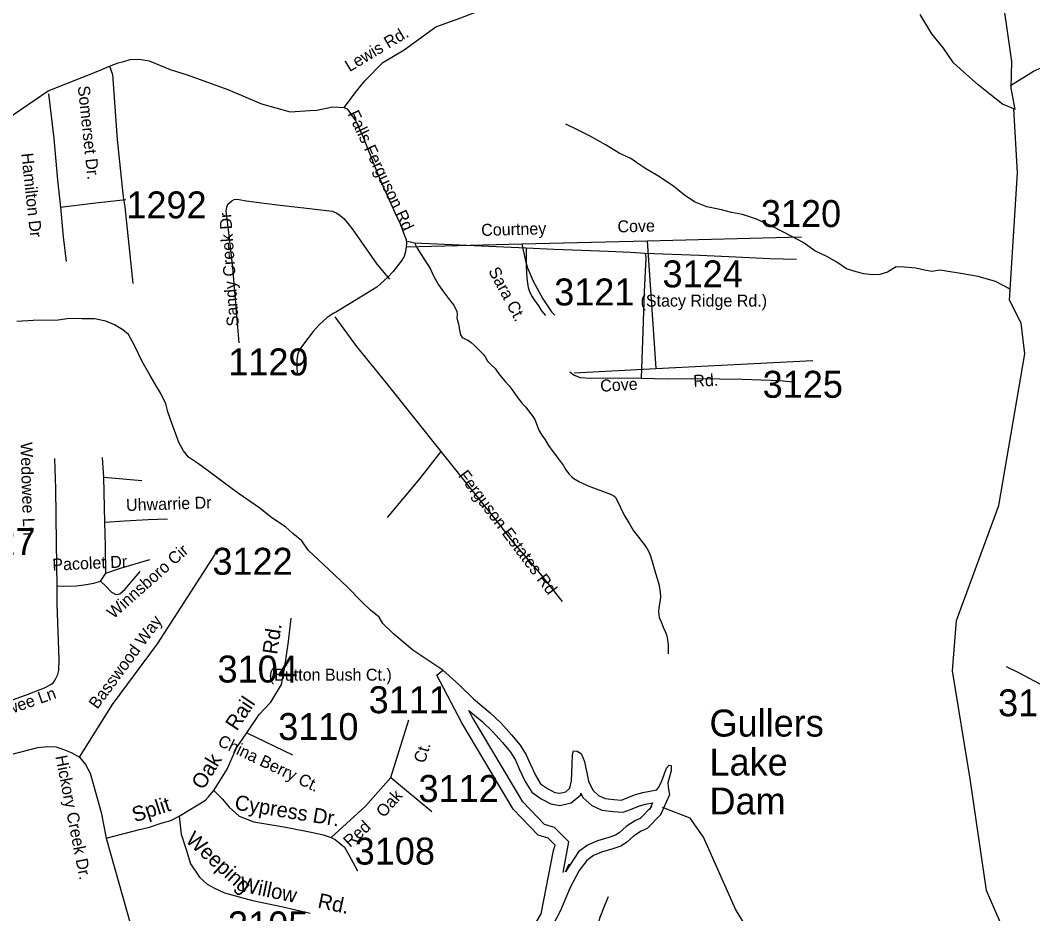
# Model space of a CAD drawing. Extents: x 1268485 to 1426702, y 514839 to 616766.
# Drawn here: x 1330300 to 1335842, y 535398 to 540290 of the extents above; entities that cross this region are included whole.
import ezdxf

# ---------------------------------------------------------------- set-up
doc = ezdxf.new("R2010")
doc.units = 0
for name, color, linetype in [('Old_Level_10', 7, 'Continuous'), ('Old_Level_11', 7, 'Continuous'), ('Old_Level_21', 7, 'Continuous'), ('Old_Level_32', 7, 'Continuous'), ('Old_Level_35', 7, 'Continuous'), ('Old_Level_58', 7, 'Continuous'), ('Old_Level_59', 7, 'Continuous'), ('Old_Level_60', 7, 'Continuous'), ('Old_Level_61', 7, 'Continuous'), ('Old_Level_62', 7, 'Continuous'), ('Old_Level_8', 7, 'Continuous')]:
    doc.layers.add(name, color=color, linetype=linetype)

msp = doc.modelspace()

# ---------------------------------------------------------------- linework, layer by layer
at = {"layer": 'Old_Level_21'}
msp.add_line((1334072.612, 536515.941), (1334072.612, 536515.941), dxfattribs=at)
at = {"layer": 'Old_Level_32'}
for p, q in [((1333731.906, 539083.111), (1334576.409, 539104.574)), ((1332412.37, 539049.577), (1333045.747, 539065.674)), ((1333045.747, 539065.674), (1333731.906, 539083.111)), ((1333731.906, 539083.111), (1333777.894, 538383.978)), ((1333777.894, 538383.978), (1334637.914, 538426.702)), ((1333332.636, 538359.564), (1333777.894, 538383.978)), ((1332328.926, 536145.055), (1332426.114, 536459.234)), ((1331540.212, 536388.17), (1331790.657, 536268.483)), ((1332328.926, 536145.055), (1332553.205, 535958.044))]:
    msp.add_line(p, q, dxfattribs=at)
for points in [[(1332072.641, 539811.815), (1332141.218, 539900.803), (1332185.275, 539959.007), (1332284.123, 540057.911), (1332401.18, 540128.185), (1332575.465, 540253.115), (1332710.731, 540302.567), (1332877.939, 540366.805), (1332933.987, 540376.856), (1332972.142, 540374.714)], [(1329888.624, 539591.849), (1329934.705, 539590.859), (1330028.307, 539619.487), (1330077.731, 539648.115), (1330452.497, 539903.986), (1330734.256, 540014.04), (1330789.108, 540038.874)], [(1330789.108, 540038.874), (1330836.646, 540056.614), (1330867.728, 540063.71), (1330902.331, 540074.922), (1330951.755, 540077.524), (1331006.382, 540067.114), (1331121.524, 540020.694), (1331212.805, 539991.129), (1331435.591, 539910.965), (1331620.802, 539832.891), (1331776.878, 539788.649), (1331884.797, 539796.313), (1331922.839, 539797.547), (1332009.243, 539815.618), (1332072.641, 539811.815)], [(1330789.108, 540038.874), (1330805.342, 539992.498), (1330830.71, 539637.446), (1330862.09, 539338.799), (1330863.79, 539322.627), (1330872.703, 539268.421), (1330915.946, 538848.576)], [(1332072.641, 539811.815), (1332089.096, 539804.719), (1332136.634, 539737.31), (1332171.374, 539662.806), (1332264.622, 539428.649), (1332350.459, 539237.698), (1332379.325, 539175.059), (1332403.527, 539110.854), (1332411.672, 539089.115), (1332414.939, 539066.927), (1332412.37, 539049.577)], [(1332412.37, 539049.577), (1332408.404, 539023.606), (1332400.781, 538997.192), (1332385.535, 538971.833), (1332341.973, 538913.721), (1332310.391, 538882.023), (1332252.672, 538829.194), (1332172.084, 538778.478), (1332030.691, 538694.44), (1332016.679, 538685.41), (1331979.807, 538661.648), (1331937, 538622.49), (1331904.036, 538585.336), (1331850.624, 538516.377), (1331832.468, 538490.271), (1331819.335, 538462.98), (1331814.679, 538433.003), (1331813.852, 538403.261), (1331816.04, 538348.03)], [(1333045.747, 539065.674), (1333064.008, 538980.288), (1333077.077, 538933.799), (1333107.57, 538861.95), (1333159.843, 538764.744), (1333207.761, 538692.896), (1333225.186, 538675.991)], [(1330624.537, 536256.112), (1330805.568, 536543.356), (1331050.713, 536876.376), (1331254.575, 537190.222), (1331364.346, 537362.838)], [(1331540.212, 536388.17), (1331607.496, 536489.156), (1331671.041, 536556.481), (1331730.849, 536653.726), (1331745.801, 536739.752), (1331768.229, 536889.361), (1331783.181, 537016.529)], [(1336803.084, 536378.338), (1336601.673, 536391.368), (1336507.681, 536396.579), (1336452.812, 536404.416), (1336384.149, 536414.822), (1336231.077, 536469.548), (1335769.175, 536714.511), (1335697.26, 536750.268)], [(1331360.427, 536072.65), (1331431.81, 536189.938), (1331484.142, 536305.885), (1331540.212, 536388.17)], [(1330042.252, 536217.02), (1330397.167, 536309.133), (1330451.794, 536314.338), (1330496.016, 536311.735), (1330542.839, 536296.12), (1330579.257, 536280.506), (1330624.537, 536256.112)], [(1330624.537, 536256.112), (1330657.295, 536215.444), (1330683.308, 536168.599), (1330699.477, 536109.735), (1330743.137, 535952.593), (1330770.627, 535812.71)], [(1332001.677, 535815.314), (1332190.621, 535987.965), (1332328.926, 536145.055)], [(1331170.685, 535932.562), (1331313.151, 536019.436), (1331329.401, 536035.696), (1331360.427, 536072.65)], [(1331360.427, 536072.65), (1331404.747, 536028.305), (1331443.159, 535981.003), (1331498.249, 535932.561), (1331578.797, 535901.296), (1331753.319, 535872.635), (1331902.334, 535843.975), (1331958.718, 535830.947), (1332001.677, 535815.314)], [(1330770.627, 535812.71), (1330953.204, 535859.609), (1331006.902, 535872.636), (1331071.341, 535893.48), (1331125.04, 535909.112), (1331170.685, 535932.562)], [(1331170.685, 535932.562), (1331181.424, 535833.554), (1331208.274, 535750.178), (1331232.438, 535672.014), (1331280.767, 535599.06), (1331323.726, 535559.978), (1331364, 535539.134), (1331417.699, 535513.079), (1331570.741, 535471.391), (1331730.497, 535437.52), (1331886.225, 535401.043)], [(1330770.627, 535812.71), (1330908.903, 535320.273), (1330939.379, 535273.543), (1330945.289, 535264.674), (1330963.017, 535248.413), (1331002.906, 535217.372), (1331053.889, 535195.21), (1331145.178, 535171.761), (1331268.686, 535143.101), (1331416.566, 535116.855)], [(1332001.677, 535815.314), (1332023.157, 535804.893), (1332074.17, 535763.205), (1332098.335, 535721.517), (1332146.664, 535632.93)]]:
    msp.add_lwpolyline(points, dxfattribs=at)
at = {"layer": 'Old_Level_35'}
for p, q in [((1332419.723, 539080.8), (1332458.581, 539071.522)), ((1332458.581, 539071.522), (1333068.611, 539043.019)), ((1330756.956, 537789.074), (1330750.292, 537895.189)), ((1330756.956, 537789.074), (1330965.289, 537770.261)), ((1330763.723, 537542.038), (1330756.956, 537789.074))]:
    msp.add_line(p, q, dxfattribs=at)
for points in [[(1330455.529, 539887.526), (1330484.032, 539643.36), (1330504.742, 539414.984), (1330519.506, 539267.397)], [(1330519.506, 539267.397), (1330696.671, 539289.082), (1330878.757, 539307.742)], [(1331498.834, 538523.263), (1331485.096, 538677.77), (1331463.463, 538933.675), (1331442.753, 539110.892), (1331426.964, 539246.687), (1331430.039, 539266.372), (1331436.909, 539282.11), (1331447.776, 539292.978), (1331458.542, 539301.795), (1331470.332, 539308.664), (1331484.173, 539310.663), (1331498.834, 539308.664), (1331537.077, 539301.436), (1331705.527, 539279.547), (1331836.453, 539265.449), (1331975.375, 539248.687), (1332008.799, 539243.765), (1332032.38, 539233.923), (1332051.142, 539220.133), (1332070.725, 539204.395), (1332087.539, 539184.71), (1332116.964, 539147.288), (1332167.202, 539074.443), (1332250.863, 538954.385), (1332320.888, 538871.698)], [(1330519.506, 539267.397), (1330534.269, 539104.945), (1330550.981, 538969.149)], [(1332458.581, 539071.522), (1332472.422, 539042.917), (1332493.952, 539007.494), (1332516.713, 538972.071), (1332535.373, 538944.492), (1332545.215, 538926.806), (1332558.954, 538897.227), (1332573.717, 538870.673), (1332588.481, 538841.196), (1332616.163, 538802.749), (1332637.796, 538773.273), (1332655.533, 538751.538), (1332673.27, 538730.93), (1332681.165, 538714.167), (1332688.957, 538696.43), (1332690.905, 538678.744), (1332689.982, 538661.007), (1332692.853, 538644.296), (1332697.876, 538627.584), (1332702.798, 538604.926), (1332705.771, 538583.241), (1332709.667, 538567.504), (1332719.509, 538553.765), (1332734.273, 538544.896), (1332752.83, 538537.002), (1332767.799, 538525.211), (1332784.408, 538510.447), (1332810.04, 538485.79), (1332833.621, 538462.209), (1332844.489, 538446.42), (1332858.227, 538423.813), (1332878.015, 538403.103), (1332898.622, 538382.444), (1332914.411, 538360.811), (1332933.174, 538335.18), (1332953.781, 538312.572), (1332976.337, 538288.94), (1332993.151, 538266.333), (1333020.628, 538227.937), (1333046.26, 538193.489), (1333067.893, 538170.83), (1333087.578, 538144.276), (1333102.342, 538126.539), (1333116.08, 538103.881), (1333127.05, 538074.353), (1333139.149, 538044.928), (1333154.63, 538018.733), (1333173.392, 537992.588), (1333191.539, 537962.395), (1333215.633, 537928.151), (1333249.877, 537883.142), (1333271.407, 537853.615), (1333286.889, 537829.419), (1333303.6, 537805.325), (1333316.416, 537791.894), (1333330.462, 537781.129), (1333360.605, 537762.982), (1333408.997, 537740.887), (1333529.773, 537695.212), (1333545.254, 537688.496), (1333555.302, 537680.448), (1333562.786, 537668.401), (1333605.027, 537581.101), (1333634.452, 537532.759), (1333656.597, 537494.517), (1333678.128, 537466.322), (1333701.606, 537436.795), (1333716.37, 537417.982), (1333731.134, 537396.502), (1333743.232, 537372.358), (1333758.611, 537327.399), (1333777.476, 537262.962), (1333790.907, 537215.954), (1333796.956, 537194.526), (1333801.672, 537156.899), (1333803.62, 537130.704), (1333800.954, 537105.892), (1333795.623, 537071.649), (1333793.675, 537053.502), (1333794.29, 537036.072), (1333797.673, 537018.643), (1333803.62, 537005.878), (1333810.387, 536990.448), (1333819.716, 536967.636), (1333830.482, 536943.439), (1333838.479, 536919.961), (1333842.58, 536898.482), (1333845.963, 536868.237), (1333846.578, 536820.613)], [(1333068.611, 539043.019), (1333220.349, 539037.021), (1333373.421, 539030.921), (1333518.392, 539026.256), (1333642.654, 539020.207), (1333721.086, 539014.825)], [(1333068.611, 539043.019), (1333068.611, 538944.338), (1333072.712, 538877.901), (1333075.992, 538850.373), (1333080.709, 538826.177), (1333088.091, 538804.082), (1333098.856, 538781.936), (1333113.62, 538759.74), (1333136.483, 538725.496), (1333153.912, 538699.352), (1333174.725, 538673.208)], [(1333721.086, 539014.825), (1333724.162, 538990.064), (1333714.422, 538802.698), (1333707.04, 538587.239), (1333697.608, 538330.207)], [(1333721.086, 539014.825), (1334017.079, 539003.444), (1334178.865, 538996.011), (1334402.987, 538985.963), (1334548.779, 538981.247)], [(1332022.64, 538666.954), (1332140.647, 538503.578), (1332307.047, 538298.834), (1332602.425, 537929.689)], [(1333308.214, 538365.065), (1333332.513, 538346.303), (1333365.423, 538334.872), (1333422.325, 538330.207), (1333581.548, 538332.206), (1333697.608, 538330.207)], [(1333697.608, 538330.207), (1333843.913, 538327.49), (1334007.031, 538328.823), (1334250.736, 538324.824), (1334458.761, 538318.109), (1334527.249, 538310.676)], [(1332602.425, 537929.689), (1332486.16, 537779.078), (1332308.995, 537568.438)], [(1332602.425, 537929.689), (1332734.273, 537765.288), (1332904.466, 537551.676), (1332998.995, 537429.618), (1333137.713, 537268.191), (1333265.768, 537107.738)], [(1330502.896, 537190.886), (1330497.873, 537428.49), (1330495.72, 537726.995), (1330488.748, 537890.524)], [(1330763.723, 537542.038), (1330869.837, 537548.805), (1331000.148, 537556.545), (1331106.16, 537560.441)], [(1330768.541, 537263.27), (1330767.619, 537410.856), (1330763.723, 537542.038)], [(1330768.541, 537263.27), (1330849.639, 537289.311), (1331008.76, 537338.524)], [(1330739.219, 537219.44), (1330768.541, 537192.475), (1330798.787, 537158.744), (1330822.368, 537146.441), (1330844.923, 537149.773), (1330874.143, 537175.61), (1330913.411, 537221.695), (1330956.164, 537271.113)], [(1330739.219, 537219.44), (1330752.137, 537237.228), (1330760.852, 537251.684), (1330768.541, 537263.27)], [(1330502.896, 537190.886), (1330605.525, 537193.603), (1330649.406, 537199.191), (1330703.232, 537208.213), (1330739.219, 537219.44)], [(1329933.262, 536450.648), (1330099.764, 536512.574), (1330328.295, 536594.8), (1330432.871, 536634.375), (1330468.345, 536653.701), (1330481.981, 536664.774), (1330491.721, 536678.051), (1330505.049, 536707.476), (1330510.996, 536730.852), (1330513.149, 536789.753), (1330502.896, 537093.384), (1330502.896, 537190.886)], [(1333426.837, 534320.055), (1333415.251, 534348.249), (1333400.077, 534403.459), (1333396.899, 534458.618), (1333396.899, 534519.211), (1333402.23, 534579.753), (1333419.455, 534666.336), (1333449.905, 534748.562), (1333461.798, 534776.706), (1333494.299, 534874.054), (1333512.651, 534951.923), (1333514.701, 535000.623), (1333508.242, 535050.399), (1333495.221, 535107.711), (1333474.716, 535171.584), (1333463.848, 535219.106), (1333456.364, 535274.315), (1333457.389, 535312.199), (1333462.926, 535341.367), (1333473.588, 535380.327), (1333500.758, 535449.584), (1333519.11, 535492.798)]]:
    msp.add_lwpolyline(points, dxfattribs=at)
at = {"layer": 'Old_Level_58'}
msp.add_line((1333803.686, 535948.304), (1333803.686, 535948.304), dxfattribs=at)
at = {"layer": 'Old_Level_59'}
for points in [[(1335744.848, 539801.712), (1335723.42, 539917.874), (1335726.732, 540064.016), (1335695.775, 540280.856), (1335673.663, 540426.891), (1335655.973, 540479.995), (1335660.395, 540533.098), (1335611.749, 540612.754), (1335550.048, 540673.849), (1335523.392, 540735.109), (1335505.86, 540757.613), (1335492.531, 540787.448), (1335488.943, 540808.056), (1335499.093, 540815.233)], [(1335720.84, 539933.12), (1335845.631, 540011.429), (1335904.173, 540036.497), (1335975.019, 540074.482), (1336096.615, 540144.252), (1336169.716, 540191.977), (1336224.67, 540233.552), (1336271.217, 540256.415), (1336335.705, 540280.56), (1336412.292, 540302.808)], [(1335747.352, 535128.073), (1335711.972, 535238.711), (1335588.144, 535526.371), (1335498.273, 536136.047), (1335402.206, 536728.852), (1335425.274, 537004.084), (1335656.265, 537632.979), (1335799.187, 538463.85), (1335778.169, 538631.736), (1335714.193, 538757.74), (1335757.689, 539454.211), (1335737.373, 539804.875)], [(1335840.451, 534554.113), (1335545.132, 534838.004), (1335461.106, 534930.94), (1335271.28, 534949.103), (1334852.256, 534839.4), (1334760.29, 534851.088), (1334580.255, 534962.996), (1334540.269, 535065.572), (1334327.323, 535237.253), (1334215.262, 535423.337), (1334040.25, 535817.448), (1333967.251, 535920.691), (1333815.455, 535979.146)]]:
    msp.add_lwpolyline(points, dxfattribs=at)
at = {"layer": 'Old_Level_60'}
for points in [[(1333219.548, 535743.754), (1333228.078, 535773.632), (1333189.691, 535812.046), (1333134.244, 535829.118), (1332997.758, 535969.969), (1332716.255, 536443.737), (1332579.769, 536704.096), (1332613.805, 536732.441), (1332700.132, 536652.727), (1332780.512, 536574.807), (1332872.786, 536499.092), (1332931.533, 536441.267), (1332988.23, 536378.623), (1333036.93, 536321.004), (1333069.841, 536268.613), (1333090.756, 536218.17), (1333121.412, 536153.528), (1333148.376, 536110.313), (1333185.798, 536084.118), (1333225.373, 536062.792), (1333251.312, 536058.179), (1333285.453, 536065.714), (1333307.906, 536084.938), (1333316.826, 536126.614), (1333320.825, 536215.146), (1333322.055, 536270.92), (1333328.412, 536290.503), (1333348.404, 536288.452), (1333370.14, 536275.739), (1333389.21, 536231.038), (1333410.843, 536124.718), (1333433.706, 536074.224), (1333465.079, 536045.671), (1333500.86, 536028.549), (1333548.638, 536023.473), (1333590.673, 536021.013), (1333616.92, 536030.292), (1333667.363, 536051.463), (1333707.553, 536062.126), (1333755.843, 536070.994), (1333784.037, 536076.992), (1333794.29, 536090.73), (1333811.002, 536125.692), (1333823.817, 536161.525), (1333836.633, 536195.769), (1333850.987, 536211.045), (1333862.982, 536209.2), (1333862.265, 536181.312), (1333844.835, 536115.183), (1333848.014, 536078.991), (1333853.345, 536049.361), (1333803.88, 535940.091)], [(1333803.88, 535940.091), (1333731.339, 535865.532), (1333699.043, 535850.563), (1333656.29, 535823.547), (1333617.535, 535788.228), (1333587.085, 535769.158), (1333542.794, 535753.625), (1333482.303, 535735.119), (1333437.909, 535716.357), (1333401.308, 535689.187), (1333359.99, 535635.822), (1333310.059, 535542.473), (1333257.156, 535415.545), (1333209.071, 535324.605), (1333163.242, 535237.714), (1333096.805, 535133.189), (1333057.471, 535112.063), (1333031.879, 535094.991), (1333014.819, 535129.136), (1333057.471, 535240.109), (1333151.305, 535398.032), (1333219.548, 535743.754)]]:
    msp.add_lwpolyline(points, dxfattribs=at)
at = {"layer": 'Old_Level_61'}
for points in [[(1333270.73, 535624.246), (1333301.766, 535792.721), (1333224.581, 535869.96), (1333169.647, 535886.874), (1333050.236, 536010.103), (1332773.559, 536475.751), (1332755.267, 536510.643), (1332828.87, 536450.247), (1332884.155, 536395.831), (1332938.834, 536335.417), (1332983.828, 536282.182), (1333011.342, 536238.383), (1333030.769, 536191.53), (1333063.743, 536121.998), (1333099.788, 536064.229), (1333151.303, 536028.169), (1333203.515, 536000.033), (1333252.69, 535991.287), (1333315.644, 536005.182), (1333367.428, 536049.518), (1333369.173, 536057.668), (1333379.52, 536034.816), (1333428.051, 535990.647), (1333482.712, 535964.49), (1333543.251, 535958.059), (1333600.059, 535954.734), (1333640.572, 535969.057), (1333688.574, 535989.203), (1333721.914, 535998.049), (1333761.37, 536005.296), (1333744.103, 535967.151)], [(1333756.85, 535985.848), (1333692.756, 535919.971), (1333667.589, 535908.307), (1333616.358, 535875.933), (1333577.702, 535840.704), (1333558.462, 535828.654), (1333522.329, 535815.983), (1333459.874, 535796.876), (1333405.117, 535773.735), (1333354.95, 535736.495), (1333283.526, 535628.513), (1333304.576, 535671.343)]]:
    msp.add_lwpolyline(points, dxfattribs=at)
at = {"layer": 'Old_Level_62'}
for points in [[(1335737.373, 539804.875), (1335675.54, 539831.035), (1335606.643, 539884.912), (1335543.794, 539936.226), (1335463.414, 540007.635), (1335408.357, 540057.155), (1335354.019, 540136.203), (1335289.837, 540215.455), (1335226.066, 540320.955)], [(1335717.921, 538817.441), (1335638.118, 538859.344), (1335542.667, 538887.538), (1335437.065, 538906.045), (1335389.185, 538912.76), (1335335.359, 538922.039), (1335289.12, 538914.759), (1335249.34, 538922.141), (1335201.46, 538932.957), (1335137.586, 538938.34), (1335093.602, 538939.211), (1335075.353, 538928.088), (1335046.953, 538910.607), (1335004.712, 538897.535), (1334964.625, 538895.894), (1334916.745, 538900.918), (1334874.914, 538912.452), (1334823.241, 538929.061), (1334770.03, 538964.638), (1334714.666, 538996.113), (1334649.255, 539026.974), (1334584.253, 539072.598), (1334519.047, 539108.379), (1334418.161, 539160.463), (1334328.963, 539199.987), (1334253.504, 539226.131), (1334193.731, 539237.152), (1334137.957, 539252.223), (1334058.294, 539268.628), (1333994.933, 539293.696), (1333937.621, 539330.963), (1333874.67, 539380.638), (1333789.881, 539438.155), (1333718.831, 539479.78), (1333685.305, 539502.644), (1333641.936, 539533.862), (1333578.473, 539561.391), (1333507.525, 539606.297), (1333416.481, 539656.586), (1333349.327, 539689.907), (1333285.966, 539721.537)], [(1332613.805, 536732.441), (1332448.123, 536840.811), (1332342.111, 536930.778), (1332285.312, 536987.68), (1332263.986, 537022.59), (1332216.824, 537059.653), (1332173.763, 537102.355), (1332089.589, 537188.579), (1331989.627, 537282.493), (1331875.925, 537389.018), (1331840.964, 537439.768), (1331791.854, 537479.343), (1331752.586, 537516.252), (1331677.64, 537566.183), (1331610.895, 537619.189), (1331494.528, 537699.518), (1331417.634, 537755.19), (1331323.207, 537826.035), (1331275.943, 537860.637), (1331220.681, 537897.854), (1331193.512, 537932.867), (1331170.443, 537975.211), (1331143.992, 538043.851), (1331123.179, 538104.137), (1331108.21, 538146.327), (1331097.137, 538189.182), (1331070.378, 538245.572), (1331043.209, 538287.966), (1331010.503, 538345.227), (1330968.16, 538421.557), (1330926.021, 538508.602), (1330893.418, 538569.964), (1330861.943, 538594.416), (1330816.524, 538623.226), (1330768.849, 538642.245), (1330707.231, 538655.779), (1330637.206, 538655.573), (1330567.078, 538656.957), (1330506.997, 538648.345), (1330370.74, 538645.321), (1330280.62, 538641.373)]]:
    msp.add_lwpolyline(points, dxfattribs=at)

# ---------------------------------------------------------------- texts
at = {"layer": 'Old_Level_10'}
for s, height, rotation, p in [('Hamilton Dr', 65.61666, 276.135114, (1330305.587, 539559.925)), ('Sandy Creek Dr', 65.61666, 93.959669, (1331497.271, 538616.253)), ('Wedowee Ln', 65.6167, 271.719236, (1330301.25, 537979.202)), ('Ferguson Estates Rd', 65.61666, 307.105833, (1332694.055, 537796.083)), ('Uhwarrie Dr', 65.61666, 1.829592, (1330880.141, 537602.829)), ('Winnsboro Cir', 65.61666, 41.537722, (1330810.483, 537009.574)), ('Pacolet Dr', 65.6167, 2.609686, (1330477.299, 537276.265)), ('Wedowee Ln', 65.6167, 19.294675, (1330018.866, 536410.172))]:
    msp.add_text(s, height=height, rotation=rotation, dxfattribs=at).set_placement(p)
at = {"layer": 'Old_Level_11'}
for s, height, rotation, p in [('Lewis Rd.', 65.6167, 30.978042, (1332102.196, 540005.182)), ('Somerset Dr.', 65.61666, 275.99835, (1330614.749, 539928.176)), ('Falls Ferguson Rd', 65.61666, 295.424094, (1332090.406, 539777.801)), ('Courtney                Cove', 65.61666, 1.455769, (1332823.878, 539108.922)), ('Sara Ct.', 65.6167, 298.269553, (1332860.273, 538917.414)), ('Cove ', 65.6167, 3.138383, (1333476.273, 538255.707)), ('Rd.', 65.6167, 2.843986, (1333985.545, 538282.346)), ('Basswood Way', 65.61666, 53.642261, (1330721.989, 536514.534)), ('Rd.', 82.0208, 81.474333, (1331705.985, 536814.384)), ('Rail', 82.0208, 56.326044, (1331484.942, 536394.792)), ('China Berry Ct.', 65.61666, 334.456928, (1331375.758, 536322.08)), ('Ct.', 65.6167, 72.811217, (1332514.208, 536218.641)), ('Hickory Creek Dr.', 65.61666, 281.118181, (1330492.036, 536259.489)), ('Oak', 82.0208, 58.674422, (1331301.851, 536071.875)), ('Cypress Dr.', 82.02083, 350.673928, (1331469.849, 535969.4)), ('Oak', 65.6167, 48.638739, (1332290.181, 535920.736)), ('Split', 82.0208, 17.924775, (1330927.395, 535898.129)), ('Red', 65.6167, 42.42, (1332105.041, 535757.946)), ('Weeping', 82.0208, 317.705681, (1331199.741, 535795.932)), ('Willow    Rd.', 82.02083, 348.029472, (1331494.464, 535523.075))]:
    msp.add_text(s, height=height, rotation=rotation, dxfattribs=at).set_placement(p)
for s, p in [('(Stacy Ridge Rd.)', (1333695.072, 538722.289)), ('(Button Bush Ct.)', (1331660.582, 536674.275))]:
    msp.add_text(s, height=65.61666, dxfattribs=at).set_placement(p)
at = {"layer": 'Old_Level_21'}
for s, p in [('Gullers', (1334072.612, 536368.304)), ('Lake', (1334072.612, 536155.049)), ('Dam', (1334072.612, 535941.795))]:
    msp.add_text(s, height=147.6375, dxfattribs=at).set_placement(p)
at = {"layer": 'Old_Level_8'}
for s, p in [('1292', (1330880.904, 539205.13)), ('3120', (1334353.608, 539157.745)), ('3124', (1333815.27, 538827.541)), ('3121', (1333222.474, 538728.417)), ('1129', (1331438.605, 538345.471)), ('3125', (1334363.556, 538222.962)), ('1227', (1329944.82, 537361.687)), ('3122', (1331352.018, 537254.046)), ('3104', (1331379.956, 536664.134)), ('3111', (1332207.022, 536496)), ('3113', (1335651.991, 536478.994)), ('3110', (1331712.069, 536349.122)), ('3112', (1332479.822, 536010.002)), ('3108', (1332130.579, 535667.511)), ('3105', (1331437.439, 535263.426))]:
    msp.add_text(s, height=147.6375, dxfattribs=at).set_placement(p)

doc.saveas('drawing.dxf')
